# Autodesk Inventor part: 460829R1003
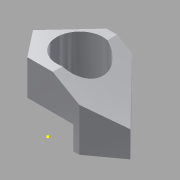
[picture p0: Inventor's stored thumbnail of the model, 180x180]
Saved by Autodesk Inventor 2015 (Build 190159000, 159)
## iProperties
Created: 2016-08
Part Number: 460829R1003
Material: 알루미늄 6061
Document SubType Name: Modeling
Designer: jio
Mass: 1465.81 g
Surface Area: 683.408 cm^2
Volume: 542.893 cm^3
Density: 2.7 g/cm^3
Appearance: 알루미늄 - 평지
Author: jio
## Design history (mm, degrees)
sketch "스케치1"
  geometry: L1 (-9.387, 55)-(34, 55); L2 (34, 55)-(104.673, -18.184); L3 (104.673, -18.184)-(54, -55); L4 (54, -55)-(-34.842, -55); L5 (-34.842, -55)-(-70, -10); L6 (-70, -10)-(-9.387, 55); C1 r 39.5 at (0, 0); 1 further point
  constraints: 12 end point, 1 centre point, 1 coincident, 1 horizontal, 1 parallel
  dimensions: "d0" = 79 diameter of C1; "d1" = 104 horizontal distance of L1.end L5.end; "d2" = 124 horizontal distance of L5.end L3.end; "d3" = 110 distance between parallel lines of L1 L4; "d4" = 45 distance from line of L4 L5.end; "d5" = 128 deg angle of L5 L4; "d6" = 99 deg angle of L5 L6; "d7" = 144 deg angle of L4 L3; "d8" = 134 deg angle of L2 L1; "d9" = 70 horizontal distance of point (0, 0) L5.end; "d10" = 55 distance from line of L4 point (0, 0)
extrude "돌출1" new body sketch "스케치1" distance "d11" = 100; taper "d12" = 0 deg
sketch "스케치2"
  geometry: 1 further point
sketch "스케치3"
  geometry: L1 (-70, 15)-(44, 15); L2 (44, 15)-(44, -55); L3 (44, -55)-(-70, -55); L4 (-70, -55)-(-70, 15); 2 further points
  constraints: 8 end point, 2 parallel, 1 horizontal, 1 perpendicular, 1 point on line
  dimensions: "d13" = 114 distance of L2.end L3.end; "d14" = 70 distance of L1.end L2.end; "d15" = 55 distance from line of L3 point (0, 0)
extrude "돌출2" cut sketch "스케치3" distance "d16" = 40; taper "d17" = 0 deg
sketch "스케치4"
  geometry: L1 (43.515, 0)-(73.131, 0); L2 (73.131, 0)-(139.515, 0); L3 (139.515, 0)-(139.515, -55.426); L4 (139.515, -55.426)-(43.515, 0); 1 further point
  constraints: 8 end point, 1 horizontal, 1 perpendicular, 1 point on line
  dimensions: "d18" = 30 deg angle of L4 L2; "d19" = 96 distance from line of L1.start L3
extrude "돌출3" cut sketch "스케치4" stored distance "d20" = 40; taper "d21" = 0 deg
node "솔리드1"
